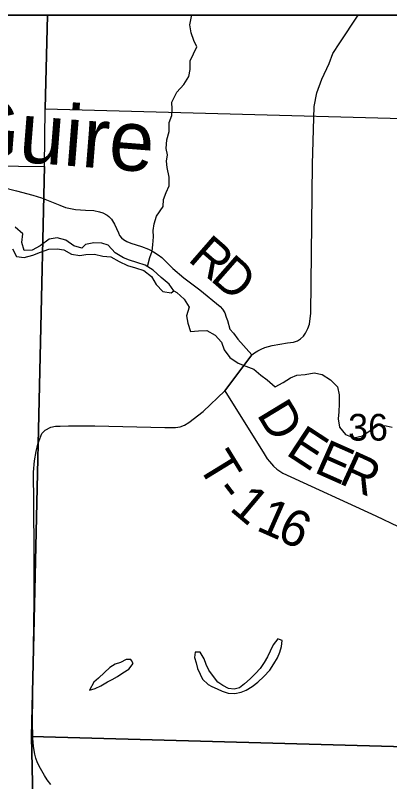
# Model space of a CAD drawing. Extents: x -1.2 to 34, y -8.5 to 22.
# Drawn here: x 5.468 to 6.054, y 19.699 to 20.9 of the extents above; entities that cross this region are included whole.
import ezdxf

# ---------------------------------------------------------------- set-up
doc = ezdxf.new("R2010")
doc.units = 0
for name, color, linetype in [('Default', 7, 'Continuous'), ('GM_X_County_Road', 7, 'Continuous'), ('GM_X_Major_River', 7, 'Continuous'), ('GM_X_Major_River_Text', 7, 'Continuous'), ('GM_X_Minor_Lake', 7, 'Continuous'), ('GM_X_Minor_River', 7, 'Continuous'), ('GM_X_Section', 7, 'Continuous'), ('GM_X_Section_Text', 7, 'Continuous'), ('GM_X_Township_Road', 7, 'Continuous'), ('GM_X_Township_Road_Text', 7, 'Continuous'), ('GM_X_Unincorporated_Text', 7, 'Continuous'), ('SH_Cut_Line', 7, 'Continuous'), ('SH_Data', 7, 'Continuous')]:
    doc.layers.add(name, color=color, linetype=linetype)

msp = doc.modelspace()

# ---------------------------------------------------------------- linework, layer by layer
at = {"layer": 'Default'}
msp.add_lwpolyline([(6.3708, 20.9), (5.5189, 20.9), (5.5152, 20.7534), (6.3638, 20.7305)], close=True, dxfattribs=at)
at = {"layer": 'GM_X_County_Road'}
msp.add_line((5.7963, 20.3112), (5.8384, 20.368), dxfattribs=at)
for points in [[(5.8384, 20.368), (5.8426, 20.3709), (5.8477, 20.3742), (5.8531, 20.3769), (5.8588, 20.3795), (5.8702, 20.3825), (5.8944, 20.3868), (5.9037, 20.3878), (5.91, 20.3899), (5.9148, 20.3928), (5.9194, 20.3971), (5.9226, 20.402), (5.9262, 20.409), (5.929, 20.4161), (5.9308, 20.4334), (5.9335, 20.6669), (5.9361, 20.7573), (5.9403, 20.7783), (5.9483, 20.8001), (5.9597, 20.8246), (5.9655, 20.8403), (5.9763, 20.8568), (6.0052, 20.9)], [(5.5242, 19.6947), (5.5184, 19.7019), (5.5142, 19.7086), (5.5077, 19.7193), (5.5031, 19.7282), (5.5004, 19.7358), (5.4989, 19.7419), (5.4967, 19.7539), (5.4956, 19.767), (5.4955, 19.7936), (5.4977, 19.9833), (5.4979, 20.0566), (5.4974, 20.1354), (5.4967, 20.184), (5.4986, 20.2019), (5.5008, 20.2163), (5.5038, 20.2278), (5.5097, 20.2444), (5.5153, 20.2498), (5.5237, 20.2547), (5.5313, 20.256), (5.5388, 20.2561), (5.5514, 20.2564), (5.593, 20.2566), (5.7022, 20.2541), (5.7112, 20.2541), (5.719, 20.2538), (5.7263, 20.2549), (5.7331, 20.2574), (5.7402, 20.2618), (5.7623, 20.2789), (5.7963, 20.3112)]]:
    msp.add_lwpolyline(points, dxfattribs=at)
at = {"layer": 'GM_X_Major_River'}
for points in [[(5.5726, 20.5349), (5.56, 20.5389), (5.5473, 20.5478), (5.5339, 20.5513), (5.5214, 20.5492), (5.5075, 20.5388), (5.4947, 20.5317), (5.4822, 20.5315), (5.4786, 20.544), (5.4799, 20.5573), (5.4683, 20.5677)], [(5.7167, 20.4679), (5.7093, 20.4788), (5.6965, 20.4892), (5.6842, 20.5007), (5.6715, 20.5085), (5.6585, 20.5128), (5.647, 20.5164), (5.6375, 20.5197), (5.6244, 20.5278), (5.6136, 20.5398), (5.604, 20.5427), (5.5915, 20.5432), (5.5782, 20.5407), (5.5726, 20.5349)], [(5.4639, 20.5339), (5.4702, 20.5222), (5.4824, 20.5205), (5.4956, 20.5238), (5.5077, 20.5285), (5.5209, 20.5337), (5.5338, 20.5339), (5.5441, 20.5322), (5.5564, 20.5255), (5.5694, 20.5235), (5.5789, 20.5252), (5.5925, 20.5254), (5.6051, 20.5226), (5.6181, 20.5213), (5.6307, 20.5143), (5.6441, 20.5077), (5.6564, 20.5041), (5.6697, 20.5001), (5.6817, 20.4905), (5.6887, 20.4781), (5.6992, 20.4672), (5.7121, 20.4652), (5.7167, 20.4679)], [(5.7167, 20.4679), (5.7213, 20.4657), (5.7328, 20.4553), (5.7403, 20.4425), (5.7363, 20.4288), (5.7384, 20.4174), (5.7424, 20.4046), (5.755, 20.4056), (5.7679, 20.4062), (5.7809, 20.3988), (5.791, 20.3879), (5.7954, 20.3755), (5.8039, 20.3639), (5.817, 20.355), (5.8293, 20.3499), (5.8415, 20.3455), (5.8527, 20.3362), (5.8623, 20.3288), (5.875, 20.3176), (5.8875, 20.3243), (5.8991, 20.3317), (5.9089, 20.336), (5.9222, 20.337), (5.9362, 20.3395), (5.9488, 20.3371), (5.9615, 20.3289), (5.9727, 20.3177), (5.9752, 20.3049), (5.9754, 20.2912), (5.9749, 20.2787), (5.9739, 20.2677), (5.9757, 20.2544), (5.985, 20.2428), (5.9984, 20.2377), (6.0116, 20.241), (6.0237, 20.2492), (6.0364, 20.2577), (6.0486, 20.2564), (6.0582, 20.2547)]]:
    msp.add_lwpolyline(points, dxfattribs=at)
at = {"layer": 'GM_X_Minor_Lake'}
for points in [[(5.7576, 19.9018), (5.7496, 19.9021), (5.7489, 19.8933), (5.7513, 19.885), (5.7536, 19.8763), (5.7575, 19.8672), (5.7614, 19.8597), (5.7702, 19.8514), (5.7759, 19.848), (5.7843, 19.8443), (5.7923, 19.8406), (5.8015, 19.8376), (5.8117, 19.837), (5.822, 19.8393), (5.8299, 19.8424), (5.839, 19.8482), (5.8477, 19.8547), (5.8574, 19.8635), (5.8665, 19.8738), (5.8732, 19.8834), (5.8785, 19.8929), (5.8822, 19.9017), (5.8848, 19.9108), (5.8858, 19.9199), (5.8816, 19.9215)], [(5.8816, 19.9215), (5.879, 19.9225), (5.8718, 19.9133), (5.8674, 19.9034), (5.8633, 19.8947), (5.858, 19.8855), (5.8516, 19.8764), (5.8441, 19.8683), (5.8358, 19.8603), (5.8272, 19.8523), (5.8192, 19.8461), (5.8109, 19.8438), (5.8022, 19.8448), (5.7934, 19.8497), (5.7854, 19.8549), (5.7788, 19.8636), (5.7711, 19.8734), (5.7673, 19.8825), (5.7638, 19.8912), (5.7576, 19.9018)], [(5.6503, 19.889), (5.6494, 19.8906), (5.6419, 19.8901), (5.6328, 19.8859), (5.6248, 19.8828), (5.6165, 19.8778), (5.6082, 19.8701), (5.5988, 19.8613), (5.5913, 19.8548), (5.5845, 19.8422)], [(5.5845, 19.8422), (5.5933, 19.845), (5.6023, 19.8492), (5.6125, 19.8554), (5.6201, 19.8588), (5.6284, 19.8639), (5.6367, 19.8692), (5.6458, 19.875), (5.6529, 19.8842), (5.6503, 19.889)]]:
    msp.add_lwpolyline(points, dxfattribs=at)
at = {"layer": 'GM_X_Minor_River'}
msp.add_lwpolyline([(5.6753, 20.5062), (5.6788, 20.5206), (5.6825, 20.5305), (5.6836, 20.54), (5.6846, 20.5529), (5.6842, 20.5628), (5.6856, 20.573), (5.6893, 20.5852), (5.6998, 20.6001), (5.7001, 20.6115), (5.7045, 20.6221), (5.7094, 20.6328), (5.7089, 20.6461), (5.7061, 20.6612), (5.7052, 20.6715), (5.7063, 20.6813), (5.7047, 20.6912), (5.7057, 20.7048), (5.709, 20.7181), (5.7092, 20.7322), (5.7133, 20.7428), (5.7136, 20.7531), (5.7135, 20.7641), (5.721, 20.7793), (5.7319, 20.7916), (5.7401, 20.8042), (5.7419, 20.8148), (5.7418, 20.8284), (5.7523, 20.8505), (5.748, 20.8604), (5.7437, 20.8725), (5.7417, 20.885), (5.7439, 20.8983), (5.7443, 20.9)], dxfattribs=at)
at = {"layer": 'GM_X_Section'}
for points in [[(5.5189, 20.9), (4.504, 20.9), (4.4978, 20.6761), (5.5138, 20.6632), (5.5152, 20.7534)], [(5.5152, 20.7534), (6.3638, 20.7305), (6.3436, 19.7459), (5.4939, 19.7699), (5.5138, 20.6632)], [(5.5138, 20.6632), (5.4939, 19.7699), (5.4956, 19.6725), (4.4756, 19.6778), (4.4978, 20.6761)], [(5.4939, 19.7699), (6.3436, 19.7459), (6.3194, 18.751), (5.4804, 18.7665), (5.4956, 19.6725)]]:
    msp.add_lwpolyline(points, close=True, dxfattribs=at)
at = {"layer": 'GM_X_Township_Road'}
msp.add_line((5.8384, 20.368), (5.7963, 20.3112), dxfattribs=at)
for points in [[(5.4477, 20.6305), (5.47, 20.6248), (5.496, 20.618), (5.5095, 20.6139), (5.5379, 20.6026), (5.5469, 20.5989), (5.5623, 20.5955), (5.5781, 20.5948), (5.5912, 20.5941), (5.6, 20.5922), (5.6054, 20.5902), (5.6119, 20.5867), (5.6148, 20.5844), (5.6189, 20.5804), (5.6237, 20.5725), (5.6296, 20.5589), (5.6315, 20.5547), (5.6344, 20.5511), (5.6377, 20.5484), (5.6427, 20.5456), (5.649, 20.543), (5.6576, 20.54), (5.666, 20.5374), (5.6768, 20.5333), (5.6848, 20.5291), (5.6921, 20.5245), (5.6975, 20.5203), (5.7039, 20.5143), (5.7147, 20.5034), (5.7322, 20.4883), (5.757, 20.4696), (5.7889, 20.4435), (5.7928, 20.4392), (5.7965, 20.4335), (5.7985, 20.427), (5.8004, 20.4216), (5.8042, 20.4079), (5.8097, 20.4019), (5.8168, 20.3926), (5.8384, 20.368)], [(5.7963, 20.3112), (5.858, 20.2125), (5.8628, 20.205), (5.8664, 20.2006), (5.8723, 20.1933), (5.8778, 20.1887), (5.8873, 20.1826), (6.0329, 20.1153), (6.0677, 20.0989)]]:
    msp.add_lwpolyline(points, dxfattribs=at)
at = {"layer": 'GM_X_Unincorporated_Text'}
msp.add_lwpolyline([(6.665, 17.7216), (6.6751, 17.7216), (6.7322, 17.7204), (7.1254, 17.7122), (7.3722, 17.707), (7.8111, 17.6977), (7.9782, 17.6941), (8.3326, 17.6871), (8.3461, 18.0704), (8.364, 18.7117), (8.3686, 18.968), (8.382, 19.7108), (8.4089, 20.6815), (8.4143, 20.9), (2.465, 20.9)], dxfattribs=at)
at = {"layer": 'SH_Cut_Line'}
msp.add_lwpolyline([(6.665, 17.7216), (6.6751, 17.7216), (6.7322, 17.7204), (7.1254, 17.7122), (7.3722, 17.707), (7.8111, 17.6977), (7.9782, 17.6941), (8.3326, 17.6871), (8.9, 17.6758), (8.9, 20.9), (2.465, 20.9)], dxfattribs=at)
at = {"layer": 'SH_Data'}
msp.add_line((2.1, 20.9), (8.9, 20.9), dxfattribs=at)

# ---------------------------------------------------------------- texts
at = {"layer": 'GM_X_Major_River_Text'}
msp.add_text('McGuire', height=0.09471, rotation=355.4839, dxfattribs=at).set_placement((5.2055, 20.6915))
at = {"layer": 'GM_X_Section_Text'}
msp.add_text('36', height=0.04186, rotation=0, dxfattribs=at).set_placement((5.9893, 20.2334))
at = {"layer": 'GM_X_Township_Road_Text'}
for s, rotation, p in [('R', 319.005, (5.7368, 20.5164)), ('D', 318.6989, (5.772, 20.4858)), ('D', 301.2686, (5.8453, 20.2746)), ('E', 326.7438, (5.89, 20.2125)), ('E', 336.0812, (5.9342, 20.1844)), ('T', 301.537, (5.7526, 20.1953)), ('R', 335.3886, (5.9729, 20.1673)), ('-', 307.2158, (5.7783, 20.154)), ('1', 320.0157, (5.802, 20.1254)), ('1', 336.1542, (5.8436, 20.0938)), ('6', 335.2645, (5.8754, 20.0797))]:
    msp.add_text(s, height=0.0568, rotation=rotation, dxfattribs=at).set_placement(p)

doc.saveas('drawing.dxf')
